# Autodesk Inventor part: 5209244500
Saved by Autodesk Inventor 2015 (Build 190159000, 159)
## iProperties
Created: 2020-07
Part Number: 5209244500
Checked By: TraceParts S.A.
Material: Generic
Catalog Web Link: www.traceparts.com
Document SubType Name: Modeling
Designer: TraceParts
Density: 1 g/cm^3
Appearance: Default
Company: TraceParts S.A.
Author: TraceParts
REFERENCE: 5209244500
DESIGN: OZEO E ECOWATT 2 RE - 5209244500
SUPPLIER: Soler & Palau
TraceParts.PartNumber: 10-20122018-119586
TraceParts.PartTitle: OZEO-E ECOWATT
TraceParts.InstanceId: 10-20122018-119586AE1K2IT6AW6N25X7GXKP23AE8
TraceParts.PartStatus: Published
TraceParts.PartVersion: 1.0.2
TRACEPARTS: TRACEPARTS
TraceParts.PartLanguage: en
TraceParts.ClassPath: SOLER_PALAU:10-20122018-119586
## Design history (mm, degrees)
feature "5209244500"
body "Solid1"
